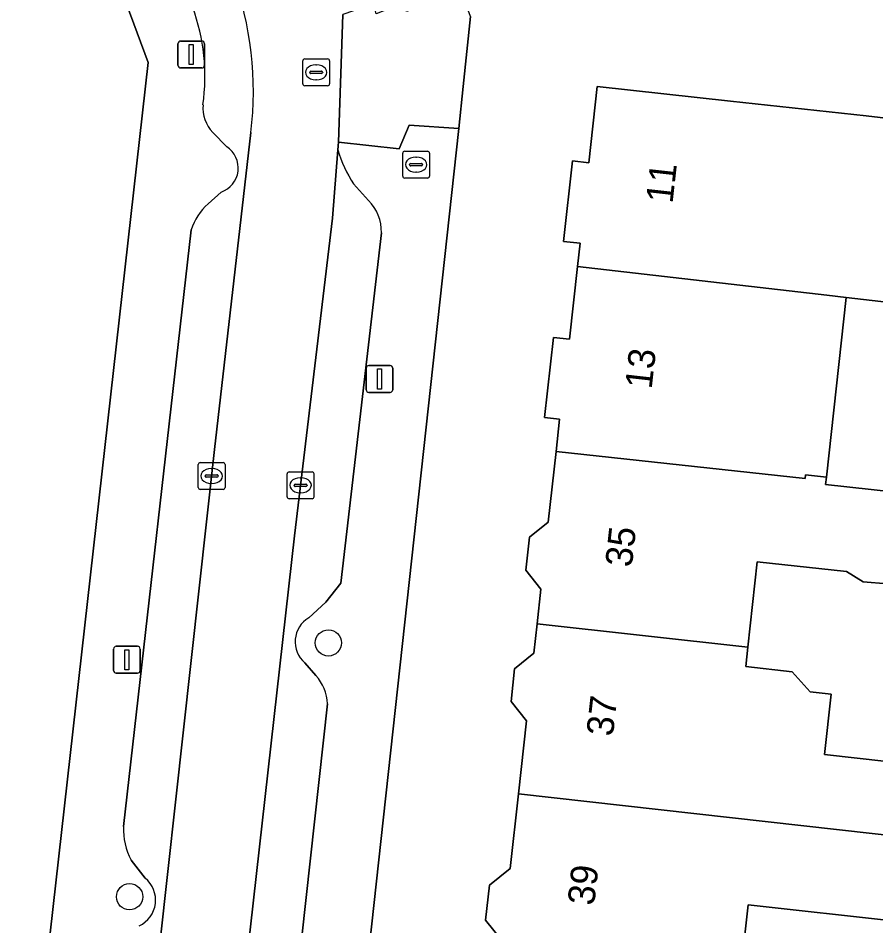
# Model space of a CAD drawing. Extents: x 161258 to 161838, y 380833 to 381727.
# Drawn here: x 161705.52 to 161737.48, y 381406.72 to 381440.54 of the extents above; entities that cross this region are included whole.
import ezdxf

# ---------------------------------------------------------------- set-up
doc = ezdxf.new("R2010")
doc.units = 0
for name, color, linetype in [('IMGEO_Boom', 7, 'Continuous'), ('IMGEO_Brandkraan', 7, 'Continuous'), ('IMGEO_Erf', 7, 'Continuous'), ('IMGEO_Kolk', 7, 'Continuous'), ('IMGEO_Lichtmast', 7, 'Continuous'), ('IMGEO_Pand', 7, 'Continuous'), ('IMGEO_Pand_nummerreeks', 7, 'Continuous'), ('IMGEO_Parkeervlak_open', 7, 'Continuous'), ('IMGEO_Rijbaan_lokaal_open', 7, 'Continuous'), ('IMGEO_Rioolput', 7, 'Continuous'), ('IMGEO_Voetpad_open', 7, 'Continuous')]:
    doc.layers.add(name, color=color, linetype=linetype)

msp = doc.modelspace()

# ---------------------------------------------------------------- linework, layer by layer
at = {"layer": 'IMGEO_Boom'}
for centre in [(161717.079, 381417.26), (161709.672, 381407.8)]:
    msp.add_circle(centre, 0.489, dxfattribs=at)
at = {"layer": 'IMGEO_Brandkraan'}
for p, q in [((161719.847, 381434.658), (161719.847, 381435.51)), ((161719.922, 381435.584), (161720.774, 381435.584)), ((161720.848, 381435.51), (161720.848, 381434.658)), ((161720.335, 381435.364), (161720.36, 381435.364)), ((161720.106, 381435.078), (161720.106, 381435.09)), ((161720.544, 381435.041), (161720.146, 381435.041)), ((161720.149, 381435.127), (161720.547, 381435.127)), ((161720.59, 381435.09), (161720.59, 381435.078)), ((161720.774, 381434.584), (161719.922, 381434.584)), ((161720.358, 381434.804), (161720.333, 381434.804))]:
    msp.add_line(p, q, dxfattribs=at)
for points in [[(161719.847, 381434.658), (161719.847, 381435.51)], [(161719.922, 381435.584), (161720.774, 381435.584)], [(161720.848, 381435.51), (161720.848, 381434.658)], [(161720.774, 381434.584), (161719.922, 381434.584)]]:
    msp.add_lwpolyline(points, dxfattribs=at)
for centre, radius, start, end in [((161719.924, 381435.508), 0.0765, 91.552, 178.448), ((161719.924, 381435.508), 0.0765, 91.552, 178.448), ((161720.772, 381435.508), 0.0765, 1.552, 88.448), ((161720.772, 381435.508), 0.0765, 1.552, 88.448), ((161720.146, 381435.087), 0.0403, 85.8775, 175.7526), ((161720.143, 381435.077), 0.0366, 178.938, 274.7102), ((161720.547, 381435.084), 0.043, 264.8664, 352.4533), ((161720.551, 381435.089), 0.0386, 1.7309, 96.639), ((161719.924, 381434.66), 0.0765, 181.552, 268.448), ((161719.924, 381434.66), 0.0765, 181.552, 268.448), ((161720.772, 381434.66), 0.0765, 271.552, 358.448), ((161720.772, 381434.66), 0.0765, 271.552, 358.448)]:
    msp.add_arc(centre, radius, start, end, dxfattribs=at)
for centre, major_axis, ratio, start_param, end_param in [((161720.334, 381435.084), (-0.387, 0.002), 0.722429, 4.712389, 7.853982), ((161720.359, 381435.084), (-0.39, 0.002), 0.717154, 1.570796, 4.712389)]:
    msp.add_ellipse(centre, major_axis=major_axis, ratio=ratio, start_param=start_param, end_param=end_param, dxfattribs=at)
at = {"layer": 'IMGEO_Erf'}
for points in [[(161649.876, 381358.212), (161669.686, 381355.721), (161676.646, 381354.846), (161685.778, 381353.698), (161689.572, 381353.221), (161700.55, 381351.841), (161703.323, 381376.439), (161703.682, 381379.623), (161710.363, 381438.89), (161702.199, 381460.88)], [(161722.379, 381440.599), (161722.102, 381438), (161721.934, 381436.431), (161715.1, 381373.857), (161714.528, 381368.72), (161712.463, 381350.189), (161712.163, 381347.496), (161746.295, 381343.062)], [(161723.554, 381406.159), (161722.937, 381406.928), (161723.08, 381408.225), (161723.856, 381408.847), (161724.161, 381411.63), (161724.46, 381414.354), (161723.885, 381415.071), (161724.019, 381416.297), (161724.734, 381416.871), (161724.855, 381417.975), (161724.997, 381419.267), (161724.437, 381419.965), (161724.572, 381421.198), (161725.274, 381421.762), (161725.563, 381424.391), (161725.695, 381425.598), (161725.137, 381425.659), (161725.464, 381428.642), (161726.065, 381428.576), (161726.363, 381431.292), (161726.458, 381432.155), (161725.841, 381432.223), (161726.17, 381435.219), (161726.781, 381435.152), (161727.093, 381438), (161732.064, 381437.454), (161737.111, 381436.9), (161739.418, 381436.634)], [(161738.638, 381429.876), (161736.369, 381430.138), (161735.633, 381423.432), (161735.604, 381423.164), (161739.002, 381422.791)], [(161737.909, 381419.467), (161737.01, 381419.535), (161736.384, 381419.919), (161733.059, 381420.284), (161732.709, 381417.1), (161732.629, 381416.374), (161734.361, 381416.184), (161735.033, 381415.436), (161735.815, 381415.35), (161735.567, 381413.097), (161737.882, 381412.843)], [(161738.324, 381406.878), (161732.721, 381407.493), (161732.352, 381404.128), (161732.263, 381403.319), (161734.83, 381403.038), (161734.516, 381400.175), (161737.512, 381399.846)]]:
    msp.add_lwpolyline(points, dxfattribs=at)
at = {"layer": 'IMGEO_Kolk'}
for p, q in [((161712.229, 381423.052), (161712.229, 381423.904)), ((161712.304, 381423.978), (161713.156, 381423.978)), ((161712.717, 381423.758), (161712.742, 381423.758)), ((161713.23, 381423.904), (161713.23, 381423.052)), ((161712.488, 381423.472), (161712.488, 381423.484)), ((161712.926, 381423.435), (161712.528, 381423.435)), ((161712.531, 381423.521), (161712.929, 381423.521)), ((161712.972, 381423.484), (161712.972, 381423.472)), ((161715.542, 381422.708), (161715.542, 381423.56)), ((161715.617, 381423.634), (161716.469, 381423.634)), ((161716.03, 381423.414), (161716.055, 381423.414)), ((161716.543, 381423.56), (161716.543, 381422.708)), ((161712.74, 381423.198), (161712.715, 381423.198)), ((161715.801, 381423.128), (161715.801, 381423.14)), ((161716.239, 381423.091), (161715.841, 381423.091)), ((161715.844, 381423.177), (161716.242, 381423.177)), ((161716.285, 381423.14), (161716.285, 381423.128)), ((161713.156, 381422.978), (161712.304, 381422.978)), ((161716.053, 381422.854), (161716.028, 381422.854)), ((161716.469, 381422.634), (161715.617, 381422.634))]:
    msp.add_line(p, q, dxfattribs=at)
for points in [[(161712.229, 381423.052), (161712.229, 381423.904)], [(161712.304, 381423.978), (161713.156, 381423.978)], [(161713.23, 381423.904), (161713.23, 381423.052)], [(161715.542, 381422.708), (161715.542, 381423.56)], [(161715.617, 381423.634), (161716.469, 381423.634)], [(161716.543, 381423.56), (161716.543, 381422.708)], [(161713.156, 381422.978), (161712.304, 381422.978)], [(161716.469, 381422.634), (161715.617, 381422.634)]]:
    msp.add_lwpolyline(points, dxfattribs=at)
for centre, radius, start, end in [((161712.306, 381423.902), 0.0765, 91.552, 178.448), ((161712.306, 381423.902), 0.0765, 91.552, 178.448), ((161713.154, 381423.902), 0.0765, 1.552, 88.448), ((161713.154, 381423.902), 0.0765, 1.552, 88.448), ((161712.528, 381423.481), 0.0403, 85.8775, 175.7526), ((161712.525, 381423.471), 0.0366, 178.938, 274.7102), ((161712.929, 381423.478), 0.043, 264.8664, 352.4533), ((161712.933, 381423.483), 0.0386, 1.7309, 96.639), ((161715.619, 381423.558), 0.0765, 91.552, 178.448), ((161715.619, 381423.558), 0.0765, 91.552, 178.448), ((161716.467, 381423.558), 0.0765, 1.552, 88.448), ((161716.467, 381423.558), 0.0765, 1.552, 88.448), ((161712.306, 381423.054), 0.0765, 181.552, 268.448), ((161712.306, 381423.054), 0.0765, 181.552, 268.448), ((161713.154, 381423.054), 0.0765, 271.552, 358.448), ((161713.154, 381423.054), 0.0765, 271.552, 358.448), ((161715.841, 381423.137), 0.0403, 85.8775, 175.7526), ((161715.838, 381423.127), 0.0366, 178.938, 274.7102), ((161716.242, 381423.134), 0.043, 264.8664, 352.4533), ((161716.246, 381423.139), 0.0386, 1.7309, 96.639), ((161715.619, 381422.71), 0.0765, 181.552, 268.448), ((161715.619, 381422.71), 0.0765, 181.552, 268.448), ((161716.467, 381422.71), 0.0765, 271.552, 358.448), ((161716.467, 381422.71), 0.0765, 271.552, 358.448)]:
    msp.add_arc(centre, radius, start, end, dxfattribs=at)
for centre, major_axis, ratio, start_param, end_param in [((161712.716, 381423.478), (-0.387, 0.002), 0.722429, 4.712389, 7.853982), ((161712.741, 381423.478), (-0.39, 0.002), 0.717154, 1.570796, 4.712389), ((161716.029, 381423.134), (-0.387, 0.002), 0.722429, 4.712389, 7.853982), ((161716.054, 381423.134), (-0.39, 0.002), 0.717154, 1.570796, 4.712389)]:
    msp.add_ellipse(centre, major_axis=major_axis, ratio=ratio, start_param=start_param, end_param=end_param, dxfattribs=at)
at = {"layer": 'IMGEO_Lichtmast'}
for p, q in [((161711.474, 381438.788), (161711.474, 381439.588)), ((161711.474, 381439.588), (161711.474, 381438.788)), ((161711.574, 381439.688), (161712.364, 381439.688)), ((161712.364, 381439.688), (161711.574, 381439.688)), ((161712.464, 381439.588), (161712.464, 381438.788)), ((161712.464, 381438.788), (161712.464, 381439.588)), ((161712.364, 381438.688), (161711.574, 381438.688)), ((161711.574, 381438.688), (161712.364, 381438.688)), ((161718.488, 381426.696), (161718.488, 381427.496)), ((161718.488, 381427.496), (161718.488, 381426.696)), ((161718.588, 381427.596), (161719.378, 381427.596)), ((161719.378, 381427.596), (161718.588, 381427.596)), ((161719.478, 381427.496), (161719.478, 381426.696)), ((161719.478, 381426.696), (161719.478, 381427.496)), ((161719.378, 381426.596), (161718.588, 381426.596)), ((161718.588, 381426.596), (161719.378, 381426.596)), ((161709.076, 381416.232), (161709.076, 381417.032)), ((161709.076, 381417.032), (161709.076, 381416.232)), ((161709.176, 381417.132), (161709.966, 381417.132)), ((161709.966, 381417.132), (161709.176, 381417.132)), ((161710.066, 381417.032), (161710.066, 381416.232)), ((161710.066, 381416.232), (161710.066, 381417.032)), ((161709.966, 381416.132), (161709.176, 381416.132)), ((161709.176, 381416.132), (161709.966, 381416.132))]:
    msp.add_line(p, q, dxfattribs=at)
for points in [[(161711.894, 381439.563), (161712.044, 381439.563), (161712.044, 381438.813), (161711.894, 381438.813), (161711.894, 381439.563)], [(161718.908, 381427.471), (161719.058, 381427.471), (161719.058, 381426.721), (161718.908, 381426.721), (161718.908, 381427.471)], [(161709.496, 381417.007), (161709.646, 381417.007), (161709.646, 381416.257), (161709.496, 381416.257), (161709.496, 381417.007)]]:
    msp.add_lwpolyline(points, dxfattribs=at)
for centre, start, end in [((161711.574, 381439.588), 90, 180), ((161711.574, 381439.588), 90, 180), ((161712.364, 381439.588), 0, 90), ((161712.364, 381439.588), 360, 90), ((161711.574, 381438.788), 180, 270), ((161711.574, 381438.788), 180, 270), ((161712.364, 381438.788), 270, 0), ((161712.364, 381438.788), 270, 0), ((161718.588, 381427.496), 90, 180), ((161718.588, 381427.496), 90, 180), ((161719.378, 381427.496), 0, 90), ((161719.378, 381427.496), 360, 90), ((161718.588, 381426.696), 180, 270), ((161718.588, 381426.696), 180, 270), ((161719.378, 381426.696), 270, 0), ((161719.378, 381426.696), 270, 0), ((161709.176, 381417.032), 90, 180), ((161709.176, 381417.032), 90, 180), ((161709.966, 381417.032), 0, 90), ((161709.966, 381417.032), 360, 90), ((161709.176, 381416.232), 180, 270), ((161709.176, 381416.232), 180, 270), ((161709.966, 381416.232), 270, 0), ((161709.966, 381416.232), 270, 0)]:
    msp.add_arc(centre, 0.1, start, end, dxfattribs=at)
at = {"layer": 'IMGEO_Pand'}
for points in [[(161726.363, 381431.292), (161735.651, 381430.217), (161736.369, 381430.138), (161738.638, 381429.876), (161739.418, 381436.634), (161737.111, 381436.9), (161732.064, 381437.454), (161727.093, 381438), (161726.781, 381435.152), (161726.17, 381435.219), (161725.841, 381432.223), (161726.458, 381432.155)], [(161725.563, 381424.391), (161734.841, 381423.385), (161734.857, 381423.524), (161735.633, 381423.432), (161736.369, 381430.138), (161735.651, 381430.217), (161726.363, 381431.292), (161726.065, 381428.576), (161725.464, 381428.642), (161725.137, 381425.659), (161725.695, 381425.598)], [(161739.002, 381422.791), (161735.604, 381423.164), (161735.633, 381423.432), (161734.857, 381423.524), (161734.841, 381423.385), (161725.563, 381424.391), (161725.274, 381421.762), (161724.572, 381421.198), (161724.437, 381419.965), (161724.997, 381419.267), (161724.855, 381417.975), (161732.709, 381417.1), (161733.059, 381420.284), (161736.384, 381419.919), (161737.01, 381419.535), (161737.909, 381419.467), (161738.476, 381419.689), (161738.67, 381419.765), (161739.247, 381420.37), (161739.525, 381421.003), (161739.623, 381421.67), (161739.424, 381422.273)], [(161732.709, 381417.1), (161724.855, 381417.975), (161724.734, 381416.871), (161724.019, 381416.297), (161723.885, 381415.071), (161724.46, 381414.354), (161724.161, 381411.63), (161738.668, 381410.013), (161738.88, 381411.952), (161737.797, 381412.071), (161737.882, 381412.843), (161735.567, 381413.097), (161735.815, 381415.35), (161735.033, 381415.436), (161734.361, 381416.184), (161732.629, 381416.374)], [(161732.352, 381404.128), (161732.721, 381407.493), (161738.324, 381406.878), (161738.668, 381410.013), (161724.161, 381411.63), (161723.856, 381408.847), (161723.08, 381408.225), (161722.937, 381406.928), (161723.554, 381406.159), (161723.44, 381405.121)]]:
    msp.add_lwpolyline(points, close=True, dxfattribs=at)
at = {"layer": 'IMGEO_Parkeervlak_open'}
for points in [[(161712.771, 381436.285), (161713.29, 381435.75)], [(161712.841, 381424.462), (161714.193, 381436.286)], [(161717.434, 381435.638), (161717.229, 381433.087), (161715.817, 381421.255), (161713.952, 381404.688), (161712.933, 381395.246), (161712.637, 381392.502), (161710.748, 381374.936)], [(161718.575, 381433.751), (161718.019, 381434.362)], [(161713.08, 381434.062), (161712.596, 381433.619)], [(161711.97, 381432.657), (161709.448, 381410.412)], [(161716.345, 381418.195), (161716.981, 381418.776), (161717.543, 381419.485), (161719.053, 381432.543)], [(161707.873, 381379.766), (161709.333, 381392.858), (161709.639, 381395.601), (161712.841, 381424.462)], [(161716.616, 381416.048), (161716.198, 381416.519)], [(161714.978, 381396.161), (161717.043, 381414.993)], [(161709.735, 381409.167), (161710.253, 381408.492)]]:
    msp.add_lwpolyline(points, dxfattribs=at)
for centre, radius, start, end in [((161701.665, 381437.812), 12.62, 353.0554, 20.1388), ((161704.815, 381438.358), 7.663, 352.1728, 19.7417), ((161713.739, 381437.206), 1.336, 175.3721, 223.5895), ((161712.773, 381434.957), 0.947, 288.9412, 56.8756), ((161721.736, 381436.838), 4.466, 195.5886, 213.6709), ((161714.088, 381431.964), 2.228, 132.0225, 161.8712), ((161717.379, 381432.579), 1.675, 358.7669, 44.41), ((161716.886, 381417.303), 1.043, 121.2595, 228.7155), ((161715.3, 381414.901), 1.746, 3.0107, 41.0596), ((161711.736, 381410.284), 2.292, 176.7944, 209.168), ((161709.582, 381407.674), 1.058, 295.0457, 50.6487)]:
    msp.add_arc(centre, radius, start, end, dxfattribs=at)
at = {"layer": 'IMGEO_Rijbaan_lokaal_open'}
msp.add_lwpolyline([(161714.193, 381436.286), (161712.841, 381424.462), (161709.639, 381395.601), (161712.933, 381395.246), (161713.952, 381404.688), (161715.817, 381421.255), (161717.229, 381433.087), (161717.434, 381435.638), (161717.456, 381435.916), (161717.622, 381440.68)], dxfattribs=at)
msp.add_arc((161701.665, 381437.812), 12.62, 353.0554, 20.1388, dxfattribs=at)
at = {"layer": 'IMGEO_Rioolput'}
for p, q in [((161716.123, 381438.096), (161716.123, 381438.948)), ((161716.198, 381439.022), (161717.05, 381439.022)), ((161717.124, 381438.948), (161717.124, 381438.096)), ((161716.425, 381438.565), (161716.823, 381438.565)), ((161716.611, 381438.802), (161716.636, 381438.802)), ((161716.382, 381438.516), (161716.382, 381438.528)), ((161716.82, 381438.479), (161716.422, 381438.479)), ((161716.634, 381438.242), (161716.609, 381438.242)), ((161716.866, 381438.528), (161716.866, 381438.516)), ((161717.05, 381438.022), (161716.198, 381438.022))]:
    msp.add_line(p, q, dxfattribs=at)
for points in [[(161716.123, 381438.096), (161716.123, 381438.948)], [(161716.198, 381439.022), (161717.05, 381439.022)], [(161717.124, 381438.948), (161717.124, 381438.096)], [(161717.05, 381438.022), (161716.198, 381438.022)]]:
    msp.add_lwpolyline(points, dxfattribs=at)
for centre, radius, start, end in [((161716.2, 381438.946), 0.0765, 91.552, 178.448), ((161716.2, 381438.946), 0.0765, 91.552, 178.448), ((161717.048, 381438.946), 0.0765, 1.552, 88.448), ((161717.048, 381438.946), 0.0765, 1.552, 88.448), ((161716.422, 381438.525), 0.0403, 85.8775, 175.7526), ((161716.827, 381438.527), 0.0386, 1.7309, 96.639), ((161716.419, 381438.515), 0.0366, 178.938, 274.7102), ((161716.823, 381438.522), 0.043, 264.8664, 352.4533), ((161716.2, 381438.098), 0.0765, 181.552, 268.448), ((161716.2, 381438.098), 0.0765, 181.552, 268.448), ((161717.048, 381438.098), 0.0765, 271.552, 358.448), ((161717.048, 381438.098), 0.0765, 271.552, 358.448)]:
    msp.add_arc(centre, radius, start, end, dxfattribs=at)
for centre, major_axis, ratio, start_param, end_param in [((161716.61, 381438.522), (-0.387, 0.002), 0.722429, 4.712389, 7.853982), ((161716.635, 381438.522), (-0.39, 0.002), 0.717154, 1.570796, 4.712389)]:
    msp.add_ellipse(centre, major_axis=major_axis, ratio=ratio, start_param=start_param, end_param=end_param, dxfattribs=at)
at = {"layer": 'IMGEO_Voetpad_open'}
for points in [[(161705.655, 381463.593), (161705.542, 381463.901), (161703.863, 381463.318), (161703.587, 381464.157), (161701.306, 381463.287), (161701.371, 381463.111), (161702.199, 381460.88), (161710.363, 381438.89), (161703.682, 381379.623), (161705.838, 381379.36), (161705.904, 381379.957), (161707.873, 381379.766)], [(161721.934, 381436.431), (161720.083, 381436.551), (161719.712, 381435.676), (161717.456, 381435.916), (161717.434, 381435.638)], [(161710.748, 381374.936), (161712.763, 381374.702), (161712.684, 381374.08), (161715.1, 381373.857), (161721.934, 381436.431)], [(161713.29, 381435.75), (161712.771, 381436.285)], [(161718.019, 381434.362), (161718.575, 381433.751)], [(161712.596, 381433.619), (161713.08, 381434.062)], [(161709.448, 381410.412), (161711.97, 381432.657)], [(161719.053, 381432.543), (161717.543, 381419.485), (161716.981, 381418.776), (161716.345, 381418.195)], [(161716.198, 381416.519), (161716.616, 381416.048)], [(161717.043, 381414.993), (161714.978, 381396.161)], [(161710.253, 381408.492), (161709.735, 381409.167)]]:
    msp.add_lwpolyline(points, dxfattribs=at)
msp.add_lwpolyline([(161722.379, 381440.599), (161722.039, 381441.525), (161719.985, 381440.791), (161719.872, 381441.096), (161718.855, 381440.706), (161718.768, 381441.075), (161717.622, 381440.68), (161717.456, 381435.916), (161719.712, 381435.676), (161720.083, 381436.551), (161721.934, 381436.431), (161722.102, 381438)], close=True, dxfattribs=at)
for centre, radius, start, end in [((161704.815, 381438.358), 7.663, 352.1728, 19.7417), ((161713.739, 381437.206), 1.336, 175.3721, 223.5895), ((161712.773, 381434.957), 0.947, 288.9412, 56.8756), ((161721.736, 381436.838), 4.466, 195.5886, 213.6709), ((161714.088, 381431.964), 2.228, 132.0225, 161.8712), ((161717.379, 381432.579), 1.675, 358.7669, 44.41), ((161716.886, 381417.303), 1.043, 121.2595, 228.7155), ((161715.3, 381414.901), 1.746, 3.0107, 41.0596), ((161711.736, 381410.284), 2.292, 176.7944, 209.168), ((161709.582, 381407.674), 1.058, 295.0457, 50.6487)]:
    msp.add_arc(centre, radius, start, end, dxfattribs=at)

# ---------------------------------------------------------------- texts
at = {"layer": 'IMGEO_Pand_nummerreeks'}
for s, rotation, p in [('11', 83.5835, (161729.9, 381433.614)), ('13', 83.5835, (161729.122, 381426.696)), ('35', 83.6576, (161728.382, 381420.056)), ('37', 83.6576, (161727.681, 381413.752)), ('39', 83.6593, (161726.981, 381407.449))]:
    msp.add_text(s, height=1, rotation=rotation, dxfattribs=at).set_placement(p)

doc.saveas('drawing.dxf')
